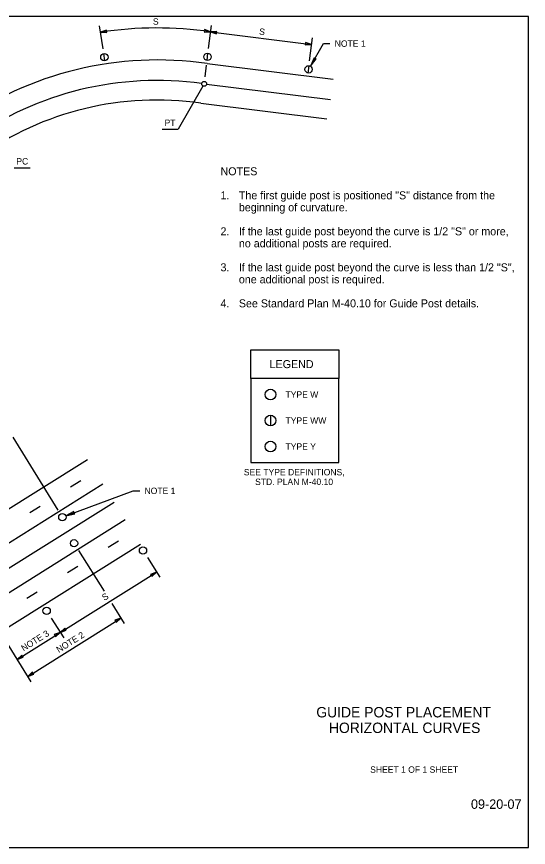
# Model space of a CAD drawing. Extents: x 99862 to 103151, y 100000 to 102076.
# Drawn here: x 101871 to 103151, y 100000 to 102076 of the extents above; entities that cross this region are included whole.
import ezdxf

# ---------------------------------------------------------------- set-up
doc = ezdxf.new("R2010")
doc.units = 0
for name, color, linetype in [('Default', 7, 'Continuous'), ('Level 1', 7, 'Continuous'), ('Level 14', 7, 'Continuous'), ('Level 15', 7, 'Continuous'), ('Level 20', 7, 'Continuous'), ('Level 4', 7, 'Continuous'), ('Level 40', 7, 'Continuous'), ('Level 60', 7, 'Continuous'), ('Level 62', 7, 'Continuous')]:
    doc.layers.add(name, color=color, linetype=linetype)

msp = doc.modelspace()

# ---------------------------------------------------------------- linework, layer by layer
at = {"layer": 'Default'}
for p, q in [((102347.6, 101958.1), (102663.1, 101918.9)), ((102346.3, 101906.7), (102655.9, 101868.1)), ((102331.9, 101859), (102647.4, 101819.8))]:
    msp.add_line(p, q, dxfattribs=at)
msp.add_circle((102340.3, 101907.4), 6.06, dxfattribs=at)
for centre, radius, start, end in [((102223.1, 101108), 859.1, 81.6721, 125.6265), ((102222.9, 101104.9), 811, 82.1094, 125.1975), ((102221.3, 101104), 763, 81.6721, 125.6265)]:
    msp.add_arc(centre, radius, start, end, dxfattribs=at)
at = {"layer": 'Level 1'}
for p, q in [((102092.2, 101965.1), (102089.4, 101983.1)), ((102347.5, 101966), (102349.8, 101984.2)), ((102600.4, 101934.6), (102602.6, 101952.8))]:
    msp.add_line(p, q, dxfattribs=at)
msp.add_lwpolyline([(99862, 99999.5), (103151, 99999.5), (103151, 102075.5), (99862, 102075.5)], close=True, dxfattribs=at)
for centre in [(102090.8, 101974.2), (102348.6, 101975.1), (102601.5, 101943.7), (101985.8, 100824.5), (102015.1, 100759.4), (102187.4, 100741.4), (101946.5, 100590.5)]:
    msp.add_circle(centre, 9.14, dxfattribs=at)
at = {"layer": 'Level 14'}
for p, q in [((102087.6, 101995.1), (102078.9, 102052.2)), ((102351.2, 101996.1), (102358.4, 102053.5)), ((102356.4, 102037.6), (102609, 102006.2)), ((102604, 101964.7), (102610.8, 102022.1)), ((102342.6, 101925.3), (102346.2, 101954.1)), ((102337.3, 101902.1), (102275.1, 101794.4)), ((102235.1, 101794.4), (102275.1, 101794.4)), ((101865.2, 101697.9), (101905.2, 101697.9)), ((101861.9, 101024.2), (101974.7, 100842.5)), ((102026.3, 100741.5), (102090.4, 100639.4)), ((102198.6, 100723.5), (102229.2, 100674.4)), ((101980.6, 100536.8), (102221.2, 100687.4)), ((101907.7, 100413.3), (101773.7, 100626.7)), ((102109.2, 100609.3), (102140.7, 100559.1)), ((101899.2, 100426.9), (102132.2, 100572.7)), ((101957.8, 100572.7), (101989.1, 100523.5)), ((101872.6, 100469.2), (101980.6, 100536.8))]:
    msp.add_line(p, q, dxfattribs=at)
for points in [[(102081.3, 102036.4), (102097.3, 102035.5), (102096.2, 102038.5), (102096.4, 102041.6)], [(102356.6, 102037.6), (102341.5, 102042.9), (102341.7, 102039.7), (102340.6, 102036.7)], [(102356.4, 102037.6), (102371.6, 102032.6), (102371.3, 102035.8), (102372.4, 102038.7)], [(102609, 102006.2), (102593.8, 102011.2), (102594.1, 102008), (102593, 102005.1)], [(102221.2, 100687.4), (102206.2, 100681.7), (102208.5, 100679.4), (102209.5, 100676.4)], [(101980.6, 100536.8), (101995.5, 100542.5), (101993.3, 100544.7), (101992.3, 100547.7)], [(101980.6, 100536.8), (101965.6, 100531.1), (101967.8, 100528.8), (101968.9, 100525.8)], [(101872.6, 100469.2), (101887.5, 100474.9), (101885.3, 100477.2), (101884.3, 100480.2)]]:
    msp.add_lwpolyline(points, close=True, dxfattribs=at)
msp.add_arc((102223.1, 101108), 939.1, 81.8263, 98.6826, dxfattribs=at)
at = {"layer": 'Level 15'}
for p, q in [((102606.2, 101951.5), (102638.8, 102008)), ((102638.8, 102008), (102654.8, 102008)), ((101994.3, 100827.7), (102163.2, 100890.5)), ((102163.2, 100890.5), (102179.2, 100890.5))]:
    msp.add_line(p, q, dxfattribs=at)
for points in [[(102606.2, 101951.5), (102620.2, 101969.8), (102617.1, 101970.4), (102615, 101972.8)], [(101994.3, 100827.7), (102016.8, 100832.9), (102014.7, 100835.3), (102014.7, 100838.5)]]:
    msp.add_lwpolyline(points, close=True, dxfattribs=at)
at = {"layer": 'Level 20'}
msp.add_line((102506.2, 101079.5), (102506.2, 101052.6), dxfattribs=at)
for centre in [(102506.3, 101131.1), (102506.3, 101066.1), (102506.3, 101001.1), (102506.3, 101001.1)]:
    msp.add_circle(centre, 13.4, dxfattribs=at)
at = {"layer": 'Level 4'}
for p, q in [((101684.6, 100740.9), (102048.6, 100968.9)), ((102006.5, 100900.1), (102031.9, 100916)), ((101720.8, 100678.6), (102086.8, 100907.9)), ((101768.9, 100645.6), (102115.3, 100862.4)), ((101904.8, 100836.4), (101930.2, 100852.3)), ((101791.7, 100597.9), (102142.8, 100818.5)), ((101830, 100536.9), (102181, 100757.5)), ((102100.7, 100749.7), (102126.1, 100765.6)), ((101999, 100686), (102024.4, 100701.9)), ((101897.3, 100622.3), (101922.7, 100638.2))]:
    msp.add_line(p, q, dxfattribs=at)
for points in [[(102132.2, 100572.7), (102117.2, 100567), (102119.5, 100564.7), (102120.5, 100561.7)], [(101899.2, 100426.9), (101914.1, 100432.6), (101911.9, 100434.8), (101910.8, 100437.8)]]:
    msp.add_lwpolyline(points, close=True, dxfattribs=at)
at = {"layer": 'Level 40'}
msp.add_lwpolyline([(102457.4, 101243.1), (102677.4, 101243.1), (102677.4, 101171.1), (102457.4, 101171.1)], close=True, dxfattribs=at)
msp.add_lwpolyline([(102457.4, 101171.1), (102457.4, 100961.1), (102677.4, 100961.1), (102677.4, 101171.1), (102457.4, 101171.1)], dxfattribs=at)
at = {"layer": 'Level 60'}
msp.add_line((103151, 102075.5), (103151, 102075.5), dxfattribs=at)

# ---------------------------------------------------------------- texts
at = {"layer": 'Level 1'}
for s, rotation, p in [('S', 0.2419, (102212.3, 102055.1)), ('S', 352.9101, (102477.1, 102030.7)), ('S', 32.0355, (102091, 100615.3)), ('NOTE 3', 31.9456, (101888.9, 100488.9)), ('NOTE 2', 32.0542, (101977, 100485))]:
    msp.add_text(s, height=16, rotation=rotation, dxfattribs=at).set_placement(p)
for s, p in [('NOTE 1', (102666.8, 102000)), ('PT', (102241.3, 101802.4)), ('PC', (101870.7, 101705.9)), ('NOTE 1', (102191.2, 100882.5))]:
    msp.add_text(s, height=16, dxfattribs=at).set_placement(p)
at = {"layer": 'Level 20'}
for s, height, p in [('NOTES', 20, (102381.2, 101679)), ('1.', 20, (102381.2, 101619)), ('The first guide post is positioned "S" distance from the', 20, (102427.1, 101619)), ('beginning of curvature.', 20, (102427.1, 101589)), ('2.', 20, (102381.2, 101529)), ('If the last guide post beyond the curve is 1/2 "S" or more,', 20, (102427.1, 101529)), ('no additional posts are required.', 20, (102427.1, 101499)), ('3.', 20, (102381.2, 101439)), ('If the last guide post beyond the curve is less than 1/2 "S",', 20, (102427.1, 101439)), ('one additional post is required.', 20, (102427.1, 101409)), ('4.', 20, (102381.2, 101349)), ('See Standard Plan M-40.10 for Guide Post details.', 20, (102427.1, 101349)), ('LEGEND', 20, (102503.9, 101197.1)), ('TYPE W', 16, (102543.7, 101123.1)), ('TYPE WW', 16, (102543.7, 101058.1)), ('TYPE Y', 16, (102543.7, 100993.1)), ('SEE TYPE DEFINITIONS,', 16, (102439.5, 100929.1)), ('STD. PLAN M-40.10', 16, (102467.7, 100905.1)), ('09-20-07', 23.62, (103007.4, 100095.8))]:
    msp.add_text(s, height=height, dxfattribs=at).set_placement(p)
at = {"layer": 'Level 62'}
for s, height, p in [('GUIDE POST PLACEMENT', 26, (102620.7, 100324.3)), ('HORIZONTAL CURVES', 26, (102652.3, 100285.3)), ('SHEET 1 OF 1 SHEET', 16, (102755.4, 100185.9))]:
    msp.add_text(s, height=height, dxfattribs=at).set_placement(p)

doc.saveas('drawing.dxf')
